// Mitsubishi GX Works2 project: NMC-24MR-4MT-F500-FX-B例程   PLC: FX1S

PROGRAM MAIN
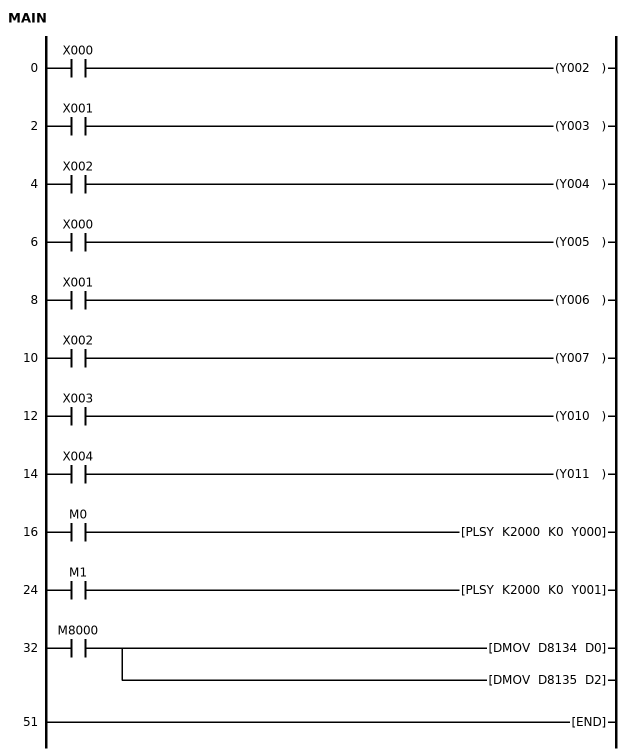
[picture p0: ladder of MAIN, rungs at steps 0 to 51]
0     LD      X000
      OUT     Y002
2     LD      X001
      OUT     Y003
4     LD      X002
      OUT     Y004
6     LD      X000
      OUT     Y005
8     LD      X001
      OUT     Y006
10    LD      X002
      OUT     Y007
12    LD      X003
      OUT     Y010
14    LD      X004
      OUT     Y011
16    LD      M0
      PLSY    K2000 K0 Y000
24    LD      M1
      PLSY    K2000 K0 Y001
32    LD      M8000
      DMOV    D8134 D0
      DMOV    D8135 D2
51    END
END_PROGRAM
